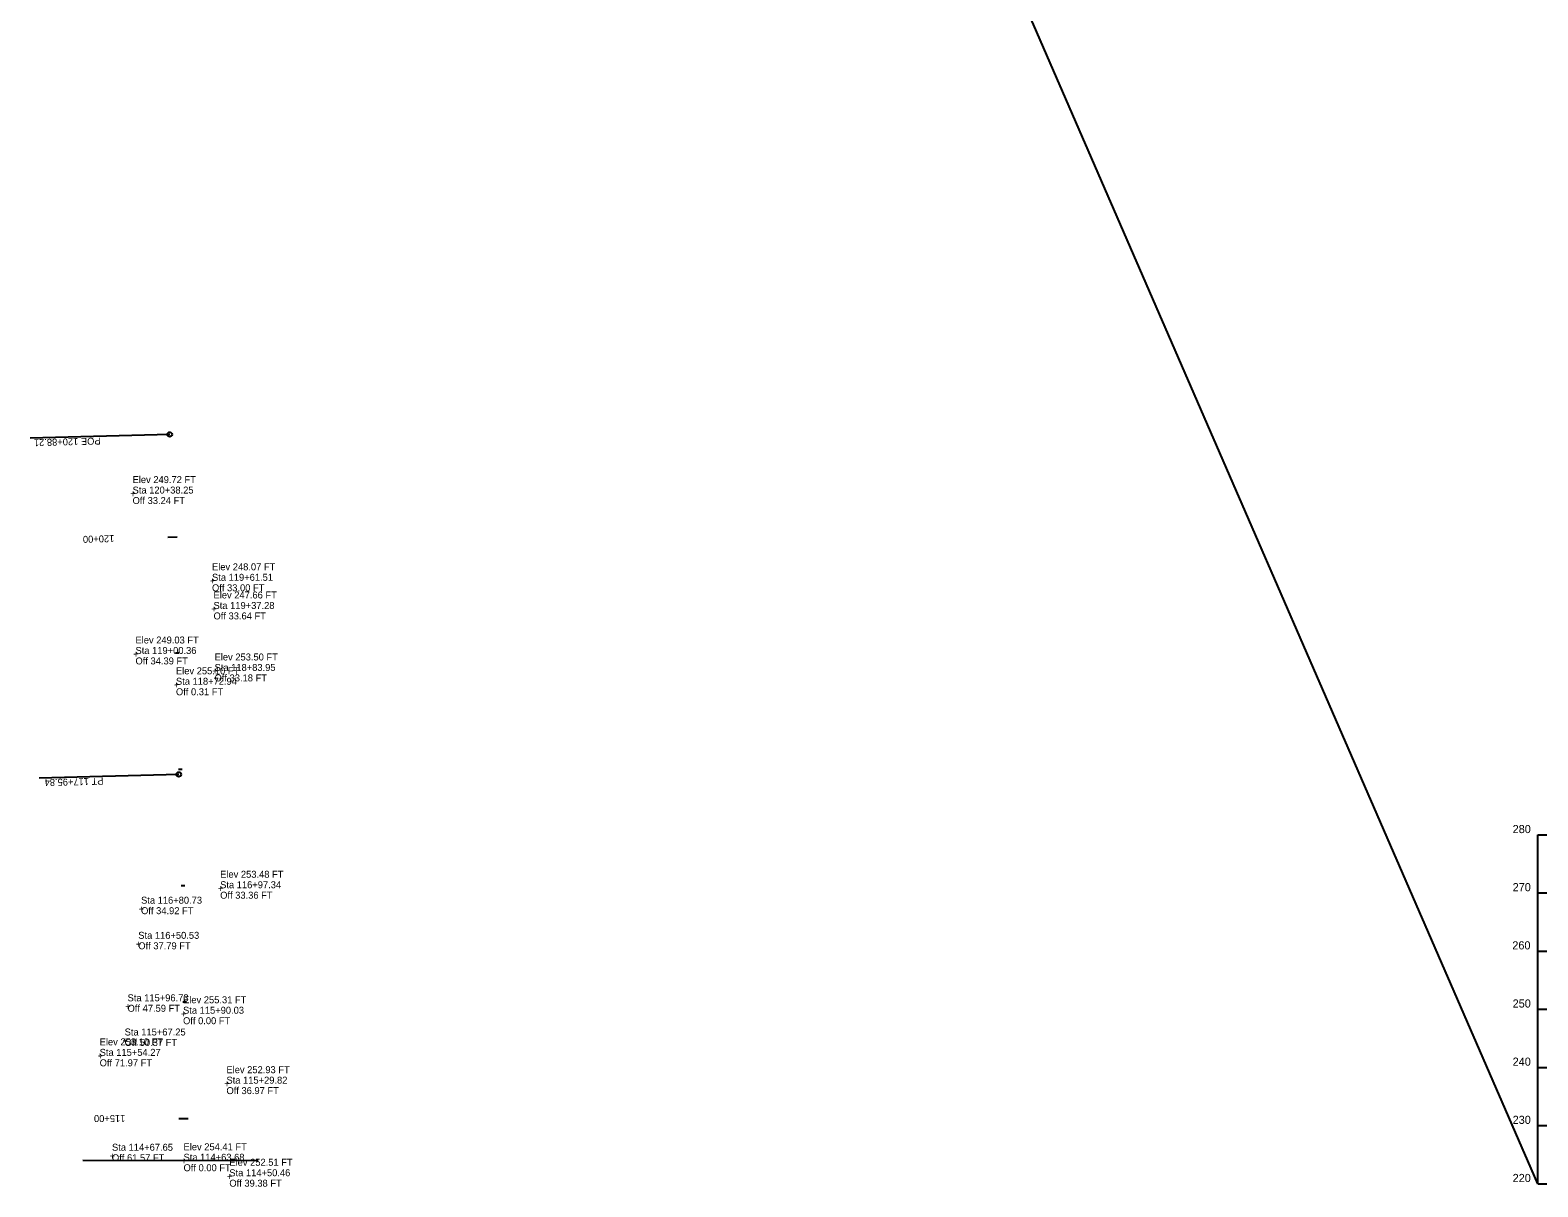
# Model space of a CAD drawing. Extents: x 1930770 to 1938778, y 596900 to 600561.
# Drawn here: x 1930796 to 1932093, y 598572 to 599566 of the extents above; entities that cross this region are included whole.
import ezdxf

# ---------------------------------------------------------------- set-up
doc = ezdxf.new("R2010")
doc.units = 0
for name, color, linetype in [('22', 7, 'Continuous'), ('E_Tract Residual', 7, 'Continuous'), ('S_CROSS_DRAIN_ANNOT', 7, 'Continuous'), ('S_DROP_INLET_ANNOT', 7, 'Continuous'), ('S_MISC_STRUCTURES_ANNOT', 7, 'Continuous'), ('S_STORM_SEWER_ANNOT', 7, 'Continuous'), ('S_UTILITY_POLE_ANNOT', 7, 'Continuous')]:
    doc.layers.add(name, color=color, linetype=linetype)

msp = doc.modelspace()

# ---------------------------------------------------------------- linework, layer by layer
at = {"layer": 'E_Tract Residual'}
for points in [[(1930916.3, 599218.8), (1930796.3, 599215.6)], [(1930914.7, 599130.5), (1930922.7, 599130.7)], [(1930924.3, 599030.7), (1930921.3, 599030.7)], [(1930924.1, 598926.5), (1930804.2, 598923.3)], [(1930927, 598930.8), (1930924, 598930.7)], [(1930929.3, 598830.8), (1930926.3, 598830.7)], [(1930930.7, 598730.8), (1930927.7, 598730.7)], [(1930924.2, 598630.7), (1930932.2, 598630.7)]]:
    msp.add_lwpolyline(points, dxfattribs=at)
for centre in [(1930916.3, 599218.8), (1930924.1, 598926.5)]:
    msp.add_circle(centre, 2, dxfattribs=at)
at = {"layer": 'S_CROSS_DRAIN_ANNOT'}
for q in [(1931507.6, 599919.1), (1932092.7, 598874.6), (1934792.7, 598574.6)]:
    msp.add_line((1932092.7, 598574.6), q, dxfattribs=at)
at = {"layer": 'S_MISC_STRUCTURES_ANNOT'}
msp.add_line((1930992.4, 598594.3), (1930841.7, 598594.6), dxfattribs=at)
at = {"layer": 'S_UTILITY_POLE_ANNOT'}
for p, q in [((1932092.7, 598874.6), (1934792.7, 598874.6)), ((1932092.7, 598874.6), (1934792.7, 598874.6)), ((1932092.7, 598824.6), (1934792.7, 598824.6)), ((1932092.7, 598774.6), (1934792.7, 598774.6)), ((1932092.7, 598724.6), (1934792.7, 598724.6)), ((1932092.7, 598674.6), (1934792.7, 598674.6)), ((1932092.7, 598624.6), (1934792.7, 598624.6))]:
    msp.add_line(p, q, dxfattribs=at)

# ---------------------------------------------------------------- texts
at = {"layer": '22'}
for s, p in [('Elev 249.72 FT ', (1930884.4, 599177)), ('Sta 120+38.25 ', (1930884.4, 599168)), ('Off 33.24 FT  ', (1930884.4, 599159)), ('Elev 248.07 FT ', (1930952.7, 599102)), ('Sta 119+61.51 ', (1930952.7, 599093)), ('Off 33.00 FT  ', (1930952.7, 599084)), ('Elev 247.66 FT ', (1930954, 599077.8)), ('Sta 119+37.28 ', (1930954, 599068.8)), ('Off 33.64 FT  ', (1930954, 599059.8)), ('Elev 249.03 FT ', (1930886.9, 599039.1)), ('Sta 119+00.36 ', (1930886.9, 599030.1)), ('Off 34.39 FT  ', (1930886.9, 599021.1)), ('Elev 253.50 FT ', (1930954.9, 599024.5)), ('Sta 118+83.95 ', (1930954.9, 599015.5)), ('Off 33.18 FT  ', (1930954.9, 599006.5)), ('Elev 253.48 FT ', (1930959.7, 598837.7)), ('Sta 116+97.34 ', (1930959.7, 598828.7)), ('Sta 116+80.73 ', (1930891.7, 598815.4)), ('Off 33.36 FT  ', (1930959.7, 598819.7)), ('Off 34.92 FT  ', (1930891.7, 598806.4)), ('Sta 116+50.53 ', (1930889.3, 598785.2)), ('Off 37.79 FT  ', (1930889.3, 598776.2)), ('Sta 115+96.73 ', (1930880.1, 598731.5)), ('Off 47.59 FT  ', (1930880.1, 598722.5)), ('Sta 115+67.25 ', (1930877.6, 598702.1)), ('Sta 115+54.27 ', (1930856.1, 598684.6)), ('Elev 253.10 FT ', (1930856.1, 598693.6)), ('Off 50.37 FT  ', (1930877.6, 598693.1)), ('Off 71.97 FT  ', (1930856.1, 598675.6)), ('Elev 252.93 FT ', (1930965.1, 598669.7)), ('Sta 115+29.82 ', (1930965.1, 598660.7)), ('Off 36.97 FT  ', (1930965.1, 598651.7)), ('Sta 114+67.65 ', (1930866.7, 598603)), ('Off 61.57 FT  ', (1930866.7, 598594)), ('Sta 114+50.46 ', (1930967.6, 598581.1)), ('Elev 252.51 FT ', (1930967.6, 598590.1)), ('Off 39.38 FT  ', (1930967.6, 598572.1))]:
    msp.add_text(s, height=6, dxfattribs=at).set_placement(p)
for rotation, p in [(1.5377, (1930882.5, 599164.9)), (1.5377, (1930950.8, 599090)), (1.5377, (1930952.1, 599065.8)), (1.5377, (1930885.1, 599027)), (1.5377, (1930953, 599012.5)), (1.045, (1930957.8, 598825.6)), (0.962, (1930889.8, 598807.8)), (0.811, (1930887.4, 598777.7)), (0.5419, (1930878.2, 598724)), (0.3945, (1930875.7, 598694.6)), (0.3296, (1930854.2, 598681.6)), (0.2074, (1930963.2, 598657.7)), (359.8965, (1930864.7, 598595.5)), (359.8106, (1930965.6, 598578.1))]:
    msp.add_text('+', height=6, rotation=rotation, dxfattribs=at).set_placement(p)
at = {"layer": 'E_Tract Residual'}
for s, rotation, p in [('POE 120+88.21', 181.5373, (1930856.8, 599216.2)), ('120+00', 181.5373, (1930868.6, 599132.3)), ('PT 117+95.84', 181.5373, (1930859.3, 598923.8)), ('115+00', 180.0581, (1930878.2, 598633.7))]:
    msp.add_text(s, height=6, rotation=rotation, dxfattribs=at).set_placement(p)
at = {"layer": 'S_DROP_INLET_ANNOT'}
for s, height, p in [('280', 7, (1932071, 598876.1)), ('280', 7, (1932071, 598876.1)), ('270', 7, (1932071, 598826.1)), ('260', 7, (1932070.7, 598776.1)), ('250', 7, (1932071, 598726.1)), ('240', 7, (1932071, 598676.1)), ('230', 7, (1932071, 598626.1)), ('220', 7, (1932071, 598576.1)), ('-', 0.0001, (1932092.7, 598574.6))]:
    msp.add_text(s, height=height, dxfattribs=at).set_placement(p)
at = {"layer": 'S_STORM_SEWER_ANNOT'}
for s, p in [('Elev 255.10 FT ', (1930921.7, 599012.6)), ('Sta 118+72.94 ', (1930921.7, 599003.6)), ('Off 0.31 FT  ', (1930921.7, 598994.6)), ('Sta 115+90.03 ', (1930927.8, 598720.8)), ('Elev 255.31 FT ', (1930927.8, 598729.8)), ('Off 0.00 FT  ', (1930927.8, 598711.8)), ('Sta 114+63.68 ', (1930928.2, 598594.4)), ('Elev 254.41 FT ', (1930928.2, 598603.4)), ('Off 0.00 FT  ', (1930928.2, 598585.4))]:
    msp.add_text(s, height=6, dxfattribs=at).set_placement(p)
for rotation, p in [(1.5373, (1930919.9, 599000.6)), (0.5084, (1930925.9, 598717.7)), (359.8767, (1930926.3, 598591.4))]:
    msp.add_text('+', height=6, rotation=rotation, dxfattribs=at).set_placement(p)

doc.saveas('drawing.dxf')
